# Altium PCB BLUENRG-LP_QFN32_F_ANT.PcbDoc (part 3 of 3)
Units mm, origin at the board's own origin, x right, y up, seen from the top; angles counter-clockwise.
Board outline 90.84 x 54.03 mm, 4 copper layers (Top Layer, G1 Layer, G2 Layer, Bottom Layer), stack 1.697 mm thick; 142 components, 101 nets, 450 pads, 662 vias.
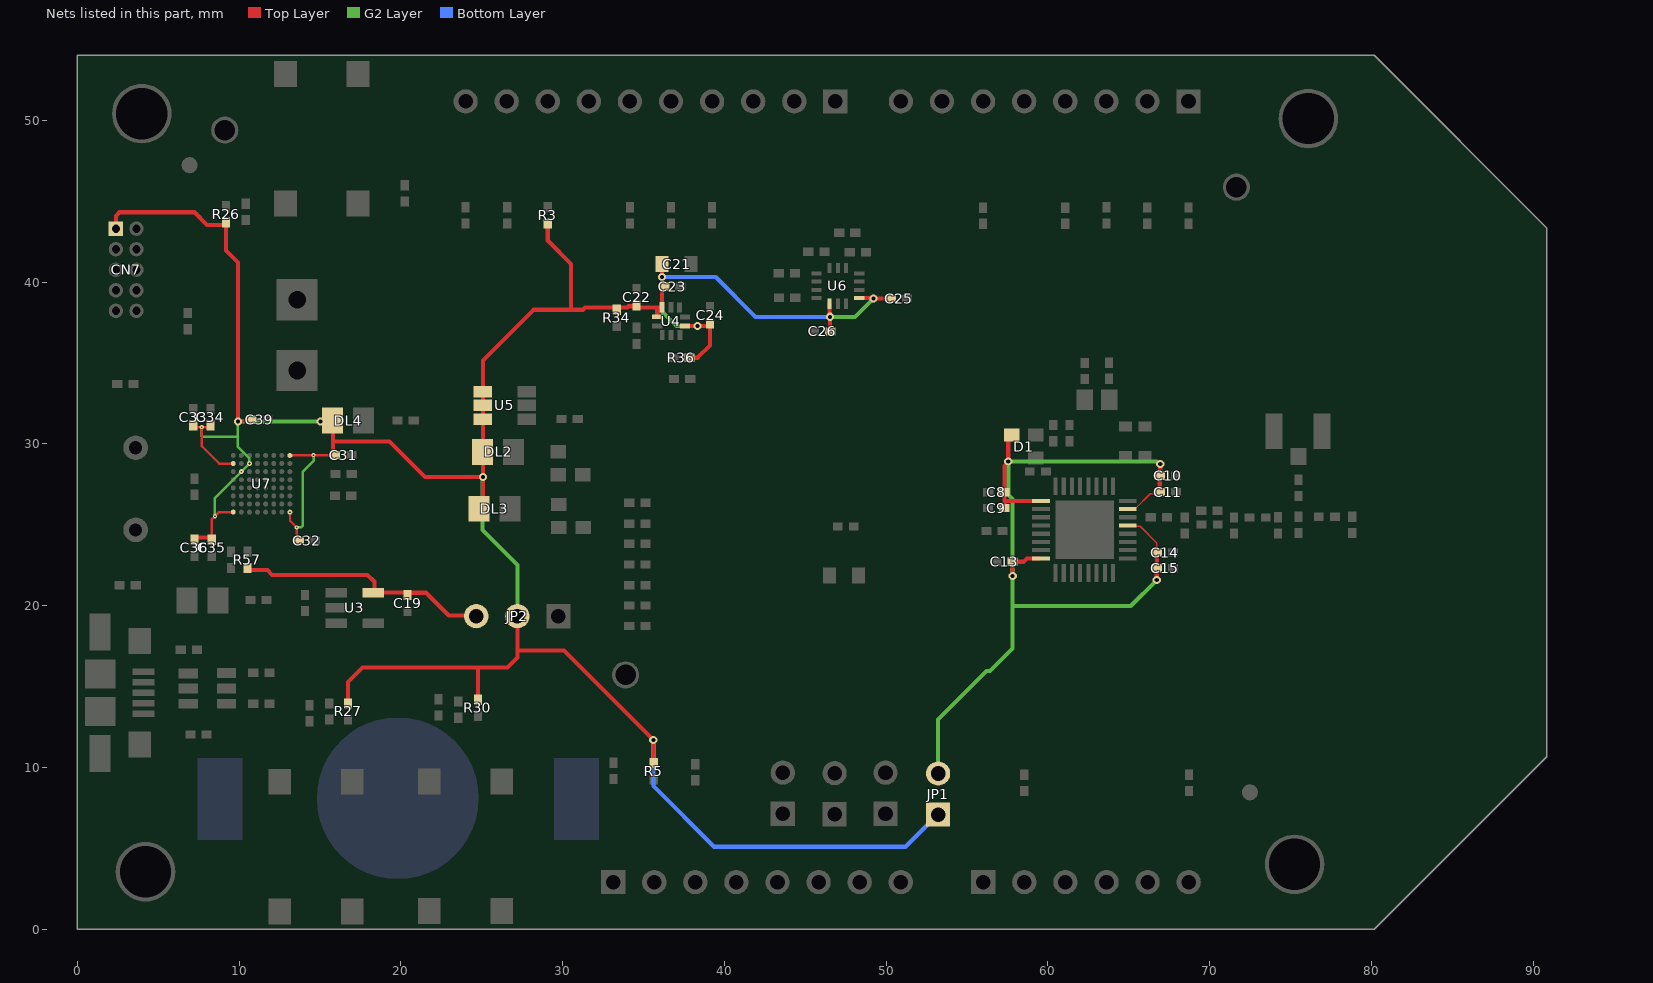
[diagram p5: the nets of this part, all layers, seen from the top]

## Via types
v1: diameter 0.508, hole 0.254, Top Layer to Bottom Layer, tented both sides, 569 vias
v2: diameter 0.254, hole 0.102, Top Layer to Bottom Layer, tented both sides, 93 vias

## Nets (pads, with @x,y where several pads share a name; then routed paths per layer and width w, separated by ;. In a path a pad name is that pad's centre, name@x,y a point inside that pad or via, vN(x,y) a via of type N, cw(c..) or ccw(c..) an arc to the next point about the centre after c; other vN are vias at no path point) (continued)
VDD1: C8.2 C9.2 C10.2 C11.2 C13.2 C14.2 C15.2 D1.3 JP1.2 pad.13 pad.15 pad.25 pad.32 | length 58.6
  Top Layer w0.102: pad.13@64.969,24.903 65.717,24.903 66.738,23.882 C14.2@66.738,23.281 C14.2@66.734,23.277 ; pad.15@65.02,25.976 65.385,25.976 66.322,26.914 C11.2@66.804,26.914 ; C15.2@66.732,22.317 C15.2@66.734,22.32
  Top Layer w0.254: C9.2@57.311,26.037 C9.2@57.299,26.037 57.306,26.043 57.306,26.507 ; D1.3@57.755,30.549 57.546,30.341 v1(57.546,28.922) 57.546,28.887 57.306,28.646 C8.2@57.306,27.02 57.306,26.507 ; v1(57.822,21.842) 57.822,22.7 C13.2@57.808,22.714 58.488,22.714 58.702,22.928 pad.32@59.458,22.928 ; pad.25@59.559,26.484 57.328,26.484 57.306,26.507 ; v1(66.732,21.582) C15.2@66.732,22.317 ; C15.2@66.734,22.32 C14.2@66.734,23.277 ; C11.2@66.804,26.914 C11.2@66.919,27.029 66.916,27.031 C10.2@66.916,28.027 66.945,28.056 v1(66.945,28.754)
  G2 Layer w0.254: JP1.2@53.213,9.627 53.213,12.962 56.211,15.96 56.417,15.96 57.822,17.365 57.822,19.972 ; v1(66.732,21.582) 65.121,19.972 57.822,19.972 ; v1(66.945,28.754) 66.876,28.754 66.708,28.922 v1(57.546,28.922) 57.546,26.867 57.822,26.591 v1(57.822,21.842) 57.822,19.972
VDD_1: C21.2 C22.2 C23.2 C24.2 C25.2 C26.2 C31.2 C32.2 C33.2 C34.2 C35.2 C36.2 C39.2 CN7.1 DL2.1 DL3.1 DL4.1 JP1.1 JP2.2 R3.1 R5.2 R26.1 R27.1 R30.1 R34.1 R36.1 U4.1 U4.6 U4.10 U5.1 U5.2 U5.3 U6.5 U6.8 U7.A1 U7.A8 U7.F7 U7.G6 U7.G8 U7.H1 | length 186.1
  Top Layer w0.102: 24.74,16.18 24.765,16.154
  Top Layer w0.152: C33.2@7.163,31.013 7.188,31.039 v2(7.696,31.039) ; C34.2@8.23,31.013 8.204,31.039 v2(7.696,31.039) ; C35.2@8.306,24.206 8.306,25.324 v2(8.509,25.527) 8.768,25.786 9.606,25.786 U7.A8@9.677,25.857 ; U7.G8@9.642,28.788 8.778,28.788 7.696,29.87 v2(7.696,31.039) ; v1(9.931,31.394) 10.516,31.394 C39.2@10.617,31.496 ; v2(13.15,25.786) 13.15,25.255 v2(13.564,24.841) C32.2@13.564,24.028 ; U7.H1@13.15,29.289 13.161,29.3 14.571,29.3 v2@14.582,29.289 ; v2(14.605,29.312) C31.2@15.799,29.312 ; DL2.1@25.07,29.515 DL2.1@25.082,29.502
  Top Layer w0.254: CN7.1@2.388,43.307 2.388,44.094 2.616,44.323 7.239,44.323 8.026,43.536 9.169,43.536 9.195,43.561 9.195,41.961 9.931,41.224 v1(9.931,31.394) ; C36.2@7.239,24.206 C35.2@8.306,24.206 ; v2@14.582,29.289 v2(14.605,29.312) ; v1(15.037,31.394) 15.799,31.394 15.799,30.152 ; C31.2@15.799,29.312 15.799,30.152 ; R27.1@16.739,14.097 16.739,15.291 17.628,16.18 24.74,16.18 26.594,16.18 27.203,16.789 JP2.2@27.203,19.355 JP2.2@27.203,19.406 ; R30.1@24.765,14.326 24.765,16.154 ; DL3.1@25.069,26.238 25.082,26.251 v1(25.082,27.958) ; DL2.1@25.07,29.515 U5.3@25.07,31.535 U5.2@25.07,32.385 U5.1@25.07,33.235 25.07,35.152 28.212,38.294 30.528,38.294 ; DL2.1@25.082,29.502 v1(25.082,27.958) ; 27.211,17.221 30.09,17.221 v1(35.608,11.703) 35.622,11.689 35.622,10.428 R5.2@35.636,10.414 ; R3.1@29.083,43.497 29.083,42.573 30.528,41.128 30.528,38.294 ; C22.2@34.564,38.425 34.576,38.437 35.839,38.437 ; C22.2@34.569,38.565 34.516,38.511 34.083,38.511 34.002,38.43 31.387,38.43 31.251,38.294 30.528,38.294 ; U4.1@35.852,37.859 35.852,38.424 35.839,38.437 ; C21.2@36.144,41.123 36.139,41.118 v1(36.139,40.315) 36.142,40.312 36.142,39.728 36.144,39.726 U4.10@36.144,38.443 36.138,38.437 35.839,38.437 ; U4.6@37.567,37.3 37.582,37.285 v1(38.346,37.285) 38.36,37.299 39.102,37.299 39.116,37.313 39.116,36.095 38.352,35.331 R36.1@37.973,35.331 ; U6.5@46.509,38.664 46.509,37.883 v1(46.534,37.857) 46.534,36.97 C26.2@46.546,36.959 ; U6.8@48.337,39.02 49.189,39.02 v1(49.218,38.991) 50.283,38.991 C25.2@50.285,38.989 ; 15.799,30.152 19.301,30.152 21.496,27.958 v1(25.082,27.958)
  G2 Layer w0.152: v2(7.696,31.039) 7.696,30.455 9.906,30.455 9.931,30.48 ; v2(8.509,25.527) 8.509,26.655 v2(10.142,28.288) v2(10.643,28.788) 10.643,29.108 9.931,29.82 9.931,30.48 ; v1@9.951,31.394 9.951,31.477 9.931,31.457 v1(9.931,31.394) 9.931,30.48 ; v2(13.564,24.841) 13.583,24.861 13.855,24.861 13.945,24.95 13.945,28.296 14.605,28.956 v2(14.605,29.312)
  G2 Layer w0.254: v1@9.951,31.394 v1(15.037,31.394) ; v1(25.082,27.958) 25.057,27.932 25.057,24.668 27.203,22.522 JP2.2@27.203,19.406 ; v1(36.139,40.315) 36.139,38.19 37.045,37.285 v1(38.346,37.285) ; v1(46.534,37.857) 48.085,37.857 v1(49.218,38.991)
  Bottom Layer w0.254: v1(35.608,11.703) 35.608,8.862 39.371,5.099 51.187,5.099 JP1.1@53.137,7.048 ; v1(36.139,40.315) 39.469,40.315 41.926,37.857 v1(46.534,37.857)
VLDO: C19.2 JP2.3 R57.2 U3.5 | length 15.7
  Top Layer w0.152: C19.2@20.411,20.813 C19.2@20.422,20.803
  Top Layer w0.254: R57.2@10.546,22.202 11.75,22.202 12.047,21.905 17.952,21.905 18.328,21.529 18.368,21.489 18.368,20.813 C19.2@20.411,20.813 ; C19.2@20.422,20.803 21.565,20.803 22.962,19.406 JP2.3@24.663,19.406
pads on no net: CN1.1 CN1.2 CN1.3 CN2.5 CN2.8 CN3.5 CN3.7 CN3.8 CN4.1 CN4.3 CN4.4 CN4.5 CN6.4 Designator9.1 Designator10.1 U3.4 U4.7 U6.9 U6.10 U6.11 U7.A2 U7.A3 U7.B3 U7.B4 U7.B5 U7.B6 U7.B7 U7.B8 U7.C4 U7.C5 U7.C6 U7.C8 U7.D1 U7.D5 U7.D6 U7.E1 U7.E2 U7.E3 U7.E4 U7.E6 U7.E8 U7.F1 U7.F6 U7.F8 U7.G3 U7.H4 U7.H5 U7.H6
copper on no net: | length 0
  Top Layer w0.305: 53.453,51.171 53.454,51.169 ; 58.533,51.171 58.534,51.169 ; 61.084,2.916 61.092,2.924 ; 63.624,2.916 63.626,2.917 ; 66.164,2.916 66.172,2.924

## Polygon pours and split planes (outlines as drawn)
no net on Top Overlay "-160559" (solid, pour order 0): 73.774,43.548 73.901,43.51 74.003,43.472 74.105,43.421 74.244,43.358 74.384,43.282 74.549,43.18 74.676,43.078 74.778,42.964 74.867,42.824 74.943,42.685 74.993,42.545 75.006,42.367 75.006,41.859 75.12,41.961 75.235,42.037 75.362,42.1 75.476,42.139 75.616,42.151 75.743,42.151 75.743,42.634 75.679,42.634 75.603,42.621 75.527,42.608 75.489,42.596 75.463,42.608 75.451,42.621 75.451,42.799 75.387,42.989 75.324,43.091 75.197,43.231 74.993,43.383 74.803,43.485 74.6,43.561 74.384,43.599 74.092,43.624 73.876,43.624 73.812,43.612 73.774,43.612 73.749,43.586 73.749,43.561
no net on Top Overlay "-160575" (solid, pour order 0): 72.06,43.218 72.136,43.167 72.263,43.129 72.39,43.078 72.568,43.015 72.72,42.951 72.911,42.862 73.063,42.786 73.215,42.697 73.393,42.57 73.533,42.456 73.711,42.278 73.825,42.139 73.914,41.974 74.016,41.758 74.079,41.542 74.092,41.275 74.092,40.488 74.168,40.564 74.295,40.665 74.435,40.767 74.663,40.881 74.892,40.957 75.032,40.983 75.032,41.554 74.943,41.542 74.841,41.504 74.778,41.478 74.739,41.453 74.727,41.465 74.714,41.605 74.701,41.821 74.689,41.948 74.638,42.1 74.549,42.266 74.447,42.418 74.219,42.659 74.003,42.837 73.825,42.964 73.635,43.066 73.381,43.155 73.139,43.231 72.949,43.269 72.606,43.282 72.326,43.282 72.2,43.269 72.111,43.243 72.06,43.231
no net on Top Overlay "-160574" (solid, pour order 0): 73.787,39.446 73.927,39.51 74.117,39.573 74.346,39.611 74.524,39.624 74.727,39.624 74.93,39.599 75.133,39.56 75.362,39.497 75.54,39.433 75.781,39.319 76.06,39.141 76.238,39.014 76.416,38.875 76.657,38.646 76.81,38.494 77,38.265 77.14,38.1 77.33,37.795 77.483,37.503 77.534,37.363 77.572,37.313 77.597,37.313 77.61,37.325 77.61,37.414 77.597,37.643 77.559,37.922 77.508,38.138 77.419,38.405 77.178,38.9 76.898,39.218 76.733,39.37 76.479,39.586 76.175,39.776 75.959,39.878 75.768,39.967 75.501,40.056 75.273,40.107 75.07,40.132 74.841,40.145 74.587,40.145 74.333,40.119 74.105,40.094 73.927,40.005 73.812,39.941 73.762,39.916 73.774,39.446
no net on Top Overlay "-160573" (solid, pour order 0): 70.383,42.405 70.434,42.393 70.498,42.38 70.625,42.342 70.815,42.278 71.006,42.215 71.171,42.151 71.45,42.024 71.615,41.948 71.882,41.808 72.149,41.631 72.39,41.427 72.555,41.262 72.72,41.084 72.809,40.945 72.898,40.767 73.038,40.424 73.088,40.17 73.114,39.84 73.127,39.535 73.114,39.116 73.101,38.938 73.266,39.065 73.393,39.179 73.482,39.256 73.66,39.383 73.774,39.446 73.774,39.916 73.698,39.878 73.685,39.891 73.698,40.183 73.673,40.411 73.609,40.691 73.508,40.957 73.368,41.212 73.228,41.415 73.088,41.58 72.949,41.719 72.707,41.935 72.466,42.088 72.212,42.24 71.92,42.367 71.666,42.456 71.323,42.52 71.095,42.545 70.841,42.532 70.612,42.507 70.434,42.469 70.371,42.443 70.371,42.418
no net on Top Overlay "-160571" (solid, pour order 0): 76.314,37.338 76.022,37.325 75.971,37.3 75.959,37.274 75.959,37.236 75.971,37.186 76.01,37.148 76.022,37.148 76.035,37.135 76.048,37.148 76.06,37.122 76.073,37.097 76.086,37.02 76.073,36.932 76.048,36.906 75.997,36.881 75.946,36.881 75.908,36.906 75.87,36.944 75.857,37.02 75.844,37.16 75.844,37.427 75.857,37.579 75.882,37.63 75.921,37.668 75.971,37.706 75.984,37.719 76.06,37.643 76.086,37.605 76.086,37.541 76.098,37.529 76.149,37.516 76.327,37.516 76.314,37.567 76.289,37.694 76.251,37.757 76.187,37.821 76.086,37.871 75.946,37.871 75.832,37.846 75.781,37.821 75.705,37.77 75.667,37.694 75.641,37.617 75.629,37.541 75.616,37.363 75.616,37.173 75.629,36.982 75.641,36.893 75.679,36.83 75.73,36.767 75.832,36.703 75.908,36.678 75.971,36.678 76.01,36.69 76.048,36.716 76.086,36.728 76.149,36.741 76.187,36.741 76.251,36.728 76.314,36.716
no net on Top Overlay "-160570" (solid, pour order 0): 74.765,37.452 74.765,37.846 74.879,37.846 75.146,37.833 75.311,37.821 75.374,37.795 75.425,37.744 75.451,37.681 75.463,37.617 75.476,37.516 75.476,37.452 75.235,37.452 75.248,37.503 75.248,37.541 75.235,37.592 75.184,37.643 75.12,37.668 74.993,37.668 74.993,37.452
no net on Top Overlay "-160569" (solid, pour order 0): 74.765,36.728 74.993,36.728 74.993,37.186 75.095,37.186 75.159,37.173 75.197,37.148 75.209,37.097 75.222,37.02 75.222,36.805 75.26,36.754 75.286,36.728 75.489,36.728 75.463,37.046 75.438,37.16 75.4,37.224 75.374,37.262 75.362,37.287 75.387,37.313 75.438,37.376 75.476,37.452 75.235,37.452 75.209,37.414 75.159,37.376 75.082,37.363 74.993,37.363 74.993,37.465 74.765,37.465
no net on Top Overlay "-160568" (solid, pour order 0): 74.079,36.728 73.876,36.728 73.876,37.846 74.066,37.846 74.117,37.833 74.155,37.795 74.27,37.465 74.346,37.249 74.358,37.211 74.397,37.211 74.409,37.236 74.409,37.846 74.612,37.846 74.612,36.728 74.346,36.728 74.143,37.338 74.117,37.363 74.092,37.363 74.079,37.351
no net on Top Overlay "-160567" (solid, pour order 0): 73.469,37.135 73.711,37.148 73.736,37.148 73.736,37.224 73.724,37.363 73.698,37.452 73.647,37.541 73.596,37.579 73.52,37.592 73.482,37.592 73.482,37.49 73.52,37.478 73.558,37.427 73.584,37.338 73.571,37.262 73.52,37.236 73.469,37.236
no net on Top Overlay "-160566" (solid, pour order 0): 73.571,36.893 73.596,36.932 73.609,36.97 73.635,36.995 73.685,37.008 73.711,36.995 73.724,36.982 73.724,36.957
no net on Top Overlay "-160565" (solid, pour order 0): 73.711,36.995 73.482,36.805 73.393,36.817 73.368,36.855 73.33,36.957 73.317,37.059 73.304,37.135 73.495,37.135 73.495,37.236 73.533,37.249 73.406,37.236 73.343,37.249 73.317,37.274 73.317,37.313 73.343,37.376 73.368,37.427 73.406,37.465 73.444,37.49 73.495,37.49 73.495,37.592 73.406,37.592 73.317,37.554 73.241,37.49 73.215,37.427 73.177,37.313 73.165,37.211 73.165,37.033 73.19,36.906 73.228,36.817 73.292,36.754 73.368,36.703 73.431,36.678 73.469,36.678 73.533,36.69 73.609,36.741 73.698,36.83 73.724,36.893 73.724,36.957 73.711,36.957
no net on Top Overlay "-160564" (solid, pour order 0): 72.479,37.567 72.606,37.567 72.606,37.071 72.619,36.944 72.619,36.868 72.657,36.83 72.707,36.817 72.758,36.817 72.796,36.843 72.847,36.893 72.86,36.982 72.86,37.148 72.873,37.554 73.012,37.567 73.012,36.716 72.974,36.728 72.911,36.741 72.873,36.728 72.822,36.716 72.784,36.703 72.746,36.69 72.695,36.678 72.619,36.69 72.555,36.728 72.504,36.792 72.492,36.83 72.479,36.919
no net on Top Overlay "-160563" (solid, pour order 0): 71.336,37.363 71.336,37.782 71.349,37.821 71.387,37.833 71.425,37.846 71.488,37.846 71.73,37.833 71.819,37.821 71.882,37.782 71.945,37.719 71.971,37.655 71.984,37.579 71.971,37.478 71.806,37.478 71.819,37.554 71.819,37.617 71.806,37.668 71.78,37.694 71.691,37.719 71.59,37.732 71.526,37.732 71.501,37.706 71.488,37.592 71.488,37.363
no net on Top Overlay "-160562" (solid, pour order 0): 71.349,36.741 71.603,36.728 71.704,36.728 71.819,36.741 71.895,36.779 71.971,36.855 72.009,36.932 72.022,37.033 72.022,37.071 71.996,37.16 71.958,37.224 71.907,37.274 71.857,37.313 71.92,37.376 71.958,37.44 71.971,37.478 71.806,37.478 71.78,37.414 71.73,37.376 71.666,37.363 71.336,37.363 71.336,37.211 71.488,37.211 71.488,37.236 71.666,37.236 71.73,37.224 71.78,37.198 71.831,37.135 71.857,37.084 71.869,37.02 71.844,36.944 71.806,36.893 71.768,36.855 71.717,36.83 71.488,36.83 71.488,37.211 71.336,37.211
no net on Top Overlay "-160561" (solid, pour order 0): 72.174,36.728 72.314,36.741 72.314,37.833 72.174,37.846
no net on Top Overlay "-160560" (solid, pour order 0): 75.73,42.151 75.882,42.139 76.048,42.1 76.213,42.024 76.391,41.91 76.53,41.796 76.632,41.694 76.759,41.554 76.873,41.402 76.975,41.237 77.064,41.059 77.102,40.996 77.114,40.996 77.14,41.021 77.127,41.224 77.102,41.402 77.064,41.554 77.025,41.656 76.886,41.897 76.746,42.075 76.67,42.164 76.543,42.278 76.403,42.393 76.289,42.469 76.213,42.52 76.022,42.583 75.895,42.621 75.794,42.634 75.73,42.634
no net on Top Overlay "-160558" (solid, pour order 0): 75.032,40.983 75.133,40.996 75.248,40.996 75.4,40.983 75.59,40.945 75.755,40.894 75.933,40.818 76.098,40.742 76.238,40.665 76.429,40.526 76.606,40.373 76.695,40.284 76.835,40.157 76.975,39.992 77.076,39.865 77.203,39.675 77.343,39.446 77.406,39.268 77.457,39.154 77.47,39.129 77.47,39.116 77.495,39.129 77.508,39.167 77.521,39.268 77.534,39.522 77.483,39.776 77.432,39.954 77.305,40.234 77.178,40.437 77.013,40.64 76.772,40.881 76.505,41.097 76.276,41.262 76.022,41.377 75.73,41.504 75.489,41.554 75.26,41.567 75.082,41.567 75.032,41.554
GND_RF on Top Layer "Mid-Layer 1-GND_RF" (solid, pour order 48): 80.236,15.529 47.809,15.529 47.809,36.085 56.549,36.085 56.549,36.179 56.643,36.085 80.273,36.085
GND on Top Layer "Mid-Layer 1-GND" (solid, pour order 46): 0.121,53.914 80.231,53.914 80.231,36.591 55.976,36.591 47.188,36.591 47.188,15.077 80.196,15.077 80.206,0.142 0.121,0.142
no net on Top Layer "NONET_TOP_LAYER_P040" (solid, pour order 40): 78.906,25.73 78.906,25.279 83.223,25.279 84.543,26.189 85.045,26.189 85.045,27.189 86.845,27.189 86.845,12.789 88.055,12.789 88.055,36.369 81.885,36.369 81.885,35.389 80.159,35.389 80.159,34.389 81.885,34.389 81.885,30.189 80.159,30.189 80.159,29.189 83.175,29.189 83.175,34.189 85.845,34.189 85.845,28.389 85.045,28.389 85.045,29.389 83.835,29.389 83.835,26.26 83.067,25.73
no net on Top Layer "Top Layer-No Net" (solid, pour order 44): 80.38,29.057
GND on Top Layer "Top Layer-GND 1" (solid, pour order 12): -5.448,53.457
GND_RF on G1 Layer "Mid-Layer 1-GND_RF" (solid, pour order 4): 80.099,15.53 47.818,15.53 47.818,36.086 56.335,36.086 56.335,36.18 56.429,36.086 80.136,36.086
GND on G1 Layer "Mid-Layer 1-GND" (solid, pour order 34): 0.127,54.153 80.169,54.153 80.169,36.579 56.007,36.579 47.193,36.579 47.193,15.049 80.047,15.049 80.058,0.127 0.127,0.127
GND_RF on Bottom Layer "Mid-Layer 1-GND_RF" (solid, pour order 52): 80.205,15.513 47.821,15.513 47.821,36.069 56.518,36.069 56.518,36.163 56.612,36.069 80.242,36.069
GND on Bottom Layer "Bottom Layer-GND" (solid, pour order 20): 0.001,54.026 80.259,54.026 80.259,36.656 55.989,36.656 47.175,36.656 47.175,15.047 80.158,15.047 80.169,0 0.001,0
GND on G2 Layer "Mid-Layer 1-GND" (solid, pour order 36): 0.127,53.899 80.169,53.899 80.169,36.576 55.982,36.576 47.193,36.576 47.193,15.062 80.158,15.062 80.169,0.127 0.127,0.127
GND_RF on G2 Layer "Mid-Layer 1-GND_RF" (solid, pour order 50): 80.2,15.517 47.817,15.517 47.817,36.073 56.513,36.073 56.513,36.167 56.607,36.073 80.237,36.073

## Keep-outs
Keep-Out Layer:
  lines w0.026: 0,0 0,54.026 80.169,54.026 90.813,43.381 90.813,10.645 80.169,0 0,0

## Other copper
Top Layer:
  rectangle net NetC43_2: 79.013,25.357 79.016,25.685
  pour cut-out: 75.131,27.145 75.844,27.145 75.844,27.409 75.132,27.409
  pour cut-out: 72.812,25.107 73.098,25.107 73.098,25.793 73.079,25.812 72.815,25.812
  pour cut-out: 69.836,24.66 70.126,24.66 70.126,26.209 70.107,26.228 69.843,26.228
  pour cut-out: 66.707,25.122 66.994,25.122 66.994,25.808 66.975,25.827 66.711,25.827
  pour cut-out: 54.091,28.016 54.104,28.003 54.104,25.256 60.11,25.256 60.176,25.322 60.097,25.401 60.097,28.056 54.13,28.056 54.104,28.03
  pour cut-out: 56.336,32.268 56.267,27.471 66.212,27.454 66.246,27.489 66.263,27.471 67.411,27.471 67.411,36.157 56.392,36.082
  region net NetC30_2: 65.408,25.585 65.581,25.625 66.045,25.723 66.045,25.217 65.851,25.256 65.409,25.348
  pour cut-out: 77.097,25.148 77.383,25.148 77.383,25.834 77.364,25.853 77.1,25.853
  region: 87.304,35.939
  region: 87.303,35.94
  pour cut-out: 53.975,23.698
  pour cut-out: 95.039,39.675
  region: 80.912,35.621

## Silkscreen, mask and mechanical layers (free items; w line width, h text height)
Top Overlay:
  circle w0.127: c73.952,39.802 r4.751
  lines w0.152: 11.148,25.076 11.148,25.301
  lines w0.254: 41.341,19.652 42.586,19.652 ; 41.349,19.644 41.349,31.62 44.854,31.62 44.854,19.644 42.594,19.644 ; 53.189,17.825 55.923,17.825 74.819,17.825 74.819,28.135 69.885,28.135 69.885,35.966 56.363,35.966 56.363,31.559 53.189,31.559 53.189,17.825
  text "PA1" at 56.515,46.99 h0.95 r90
  text "PA7" at 54.229,46.863 h0.95 r90
  text "GND" at 32.131,46.736 h0.95 r90
  text "PB9" at 42.291,46.736 h0.95 r90
  text "PB8" at 44.958,46.736 h0.95 r90
  text "PA5" at 47.371,46.736 h0.95 r90
  text "PA4" at 51.435,46.736 h0.95 r90
  text "PA6" at 58.928,46.736 h0.95 r90
  text "PB0" at 64.008,46.736 h0.95 r90
  text "PA9" at 66.675,46.736 h0.95 r90
  text "PA8" at 69.215,46.736 h0.95 r90
  text "PA11" at 24.511,46.101 h0.95 r90
  text "PB14" at 27.178,46.101 h0.95 r90
  text "VBAT" at 29.591,45.974 h0.95 r90
  text "PA13" at 34.671,45.974 h0.95 r90
  text "PA14" at 37.211,45.974 h0.95 r90
  text "PA15" at 39.751,45.974 h0.95 r90
  text "PA13" at 61.468,45.974 h0.95 r90
  text "0" at 28.169,38.075 h0.23
  text "O" at 15.951,37.579 h0.19
  text "O" at 24.765,33.782 h0.18
  text "O" at 13.462,25.578 h0.18
  text "O" at 59.589,21.457 h0.25
  text "USB" at 25.019,21.031 h0.95 r90
  text "BAT" at 30.226,21.031 h0.95 r90
  text "FOR EVALUATION ONLY" at 42.454,20.076 h0.6 r90
  text "NOT FCC APPROVED" at 43.47,20.076 h0.6 r90
  text "FOR RESALE" at 44.486,20.076 h0.6 r90
  text "U1" at 63.851,20.042 h1.02
  text "BLUENRG-LP QFN32" at 48.244,15.826 h1.14
  text "vers 2" at 48.311,14.616 h0.76
  text "1" at 54.635,6.502 h0.57
  text "1" at 41.961,6.185 h0.57
  text "1" at 51.054,4.953 h0.57
  text "1" at 46.939,4.902 h0.57
  text "PB5" at 56.642,4.699 h0.95 r90
  text "VBAT" at 41.427,4.651 h0.95 r90
  text "VBAT" at 36.195,4.572 h0.95 r90
  text "RSTN" at 38.735,4.572 h0.95 r90
  text "PB2" at 59.055,4.572 h0.95 r90
  text "PB3" at 61.595,4.572 h0.95 r90
  text "PA12" at 64.135,4.572 h0.95 r90
  text "PB7" at 66.675,4.572 h0.95 r90
  text "PB4" at 69.215,4.572 h0.95 r90
  text "GND" at 43.942,4.343 h0.95
  text "GND" at 47.625,4.318 h0.95
Mechanical 1:
  lines w0.025: -0.013,0 ccw(c0,0) 0,-0.013 ; -0.013,0 ccw(c0,0) 0,-0.013 ; -0.013,0 -0.013,54.026 ; -0.013,54.026 cw(c0,54.026) 0,54.039 ; -0.013,54.026 cw(c0,54.026) 0,54.039 ; 0,-0.013 80.169,-0.013 ; 0,54.039 80.169,54.039 ; 80.169,-0.013 ccw(c80.169,0) 80.178,-0.009 ; 80.169,-0.013 ccw(c80.169,0) 80.178,-0.009 ; 80.169,54.039 cw(c80.169,54.026) 80.178,54.035 ; 80.169,54.039 cw(c80.169,54.026) 80.178,54.035 ; 80.178,-0.009 90.783,10.596 90.842,10.866 90.842,43.371 80.178,54.035 ; 0.013,0.013 80.163,0.013 90.822,10.671 90.822,43.355 80.163,54.013 0.013,54.013 0.013,0.013 ; 88.875,8.688 ccw(c88.866,8.697) 88.879,8.697 cw(c88.866,8.697) 88.875,8.688 ; 88.875,45.338 cw(c88.866,45.329) 88.879,45.329 ccw(c88.866,45.329) 88.875,45.338
  text ".Designator" at 58.518,21.887 h1.43 r90
  text ".Designator" at 58.528,21.885 h1.43 r90
  text ".Comment" at 56.295,21.252 h1.43 r90
  text ".Comment" at 56.306,21.25 h1.43 r90
Mechanical 13:
  lines w0.025: 13.391,25.33 13.641,25.58
Drill Drawing:
  lines w0.254: 7.023,-82.194 101.892,-82.194 ; 7.023,-82.067 7.023,-36.347 ; 7.023,-36.22 101.892,-36.22 ; 7.15,-76.987 101.765,-76.987 ; 7.15,-73.177 101.765,-73.177 ; 7.15,-69.367 101.765,-69.367 ; 7.15,-65.557 101.765,-65.557 ; 7.15,-61.747 101.765,-61.747 ; 7.15,-57.937 101.765,-57.937 ; 7.15,-54.127 101.765,-54.127 ; 7.15,-50.317 101.765,-50.317 ; 7.15,-46.507 101.765,-46.507 ; 7.15,-46.38 101.765,-46.38 ; 7.15,-41.427 101.765,-41.427 ; 7.15,-41.3 101.765,-41.3 ; 11.151,-63.652 12.421,-63.652 ; 11.151,-56.667 12.421,-55.397 ; 11.151,-55.397 12.421,-56.667 ; 11.151,-52.222 12.421,-52.222 ; 11.786,-64.287 11.786,-63.017 ; 11.786,-52.857 11.786,-51.587 ; 16.421,-76.987 16.421,-41.427 ; 16.548,-76.987 16.548,-41.427 ; 37.863,-76.987 37.863,-41.427 ; 58.352,-82.067 58.352,-41.427 ; 72.449,-82.067 72.449,-41.427 ; 101.892,-82.067 101.892,-36.347 ; 11.151,-68.097 11.151,-66.827 ; 11.151,-68.097 12.421,-68.097 ; 11.151,-68.097 12.421,-66.827 ; 11.151,-66.827 12.421,-66.827 ; 11.151,-66.827 12.421,-68.097 ; 12.421,-68.097 12.421,-66.827 ; 7.15,-82.067 101.765,-82.067 101.765,-36.347 7.15,-36.347 7.15,-82.067 ; 11.151,-75.336 11.151,-74.828 11.786,-75.463 12.421,-74.828 12.421,-75.336 11.786,-74.701 11.151,-75.336 ; 11.151,-71.272 11.786,-70.637 12.421,-71.272 11.786,-71.907 11.151,-71.272 ; 11.151,-59.842 11.151,-59.207 11.786,-59.207 11.786,-60.477 12.421,-60.477 12.421,-59.842 11.151,-59.842 ; 11.151,-52.857 11.151,-51.587 12.421,-51.587 12.421,-52.857 11.151,-52.857 ; 11.151,-48.666 11.151,-48.158 11.532,-47.777 12.04,-47.777 12.421,-48.158 12.421,-48.666 12.04,-49.047 11.532,-49.047 11.151,-48.666
  text ".Legend" at 7.15,-36.347 h0.64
